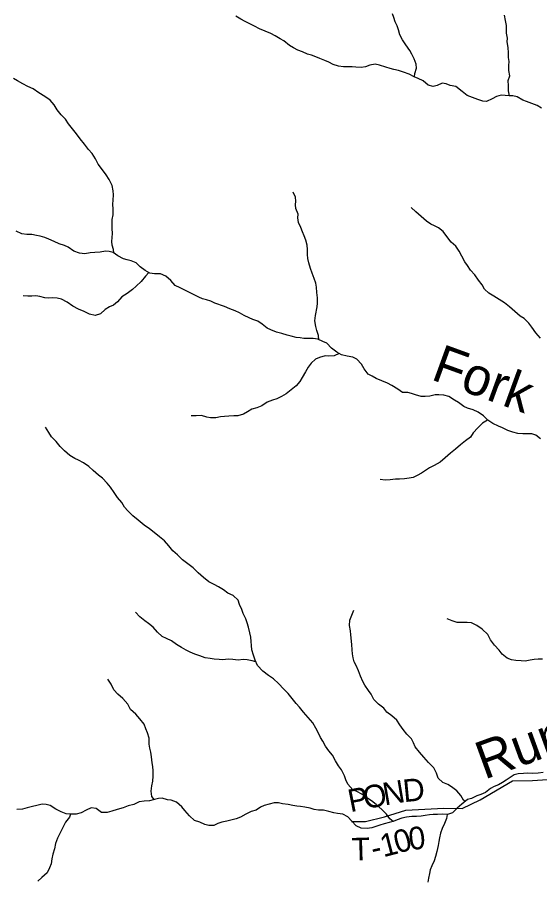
# Model space of a CAD drawing. Extents: x 1624196 to 2029251, y 146837 to 440034.
# Drawn here: x 1775938 to 1782867, y 237961 to 249407 of the extents above; entities that cross this region are included whole.
import ezdxf

# ---------------------------------------------------------------- set-up
doc = ezdxf.new("R2010")
doc.units = 0
for name, color, linetype in [('GM_X_Minor_River', 7, 'Continuous'), ('GM_X_Minor_River_Text', 7, 'Continuous'), ('GM_X_Township_Road', 7, 'Continuous'), ('GM_X_Township_Road_Text', 7, 'Continuous')]:
    doc.layers.add(name, color=color, linetype=linetype)

msp = doc.modelspace()

# ---------------------------------------------------------------- linework, layer by layer
at = {"layer": 'GM_X_Minor_River'}
for points in [[(1782892, 248200), (1782832, 248237), (1782762, 248261), (1782691, 248290), (1782641, 248308), (1782569, 248351), (1782511, 248363), (1782461, 248363), (1782407, 248368), (1782357, 248372), (1782293, 248356), (1782238, 248323), (1782162, 248291), (1782111, 248295), (1782045, 248316), (1781975, 248340), (1781903, 248367), (1781839, 248423), (1781753, 248490), (1781681, 248500), (1781627, 248525), (1781575, 248533), (1781509, 248501), (1781454, 248489), (1781386, 248504), (1781320, 248562), (1781254, 248593), (1781200, 248617), (1781136, 248652), (1781062, 248680), (1780992, 248699), (1780932, 248713), (1780882, 248729), (1780828, 248746), (1780740, 248770), (1780686, 248785), (1780615, 248771), (1780557, 248749), (1780497, 248742), (1780428, 248744), (1780378, 248748), (1780328, 248751), (1780264, 248749), (1780198, 248759), (1780128, 248780), (1780068, 248812), (1780018, 248832), (1779951, 248861), (1779899, 248881), (1779841, 248902), (1779789, 248918), (1779723, 248948), (1779661, 248971), (1779603, 249001), (1779549, 249034), (1779475, 249096), (1779425, 249119), (1779359, 249159), (1779299, 249190), (1779227, 249222), (1779149, 249253), (1779085, 249289), (1779031, 249315), (1778961, 249352), (1778903, 249382), (1778837, 249423)], [(1781205, 248615), (1781209, 248659), (1781233, 248731), (1781227, 248783), (1781200, 248854), (1781170, 248916), (1781144, 248968), (1781091, 249041), (1781045, 249107), (1781011, 249172), (1780992, 249242), (1780976, 249294), (1780952, 249347), (1780930, 249403), (1780913, 249453)], [(1782465, 248363), (1782454, 248430), (1782452, 248498), (1782448, 248566), (1782469, 248630), (1782457, 248702), (1782458, 248766), (1782460, 248821), (1782452, 248875), (1782455, 248937), (1782447, 249007), (1782436, 249079), (1782438, 249130), (1782426, 249196), (1782427, 249246), (1782427, 249296), (1782411, 249362), (1782402, 249435)], [(1777220, 246278), (1777212, 246324), (1777198, 246382), (1777194, 246432), (1777197, 246484), (1777199, 246539), (1777197, 246603), (1777198, 246721), (1777209, 246787), (1777209, 246859), (1777207, 246928), (1777210, 246980), (1777214, 247050), (1777211, 247104), (1777195, 247176), (1777157, 247253), (1777118, 247315), (1777070, 247384), (1777012, 247458), (1776976, 247530), (1776929, 247601), (1776883, 247653), (1776829, 247724), (1776771, 247792), (1776722, 247861), (1776672, 247927), (1776618, 247994), (1776576, 248056), (1776521, 248113), (1776467, 248179), (1776425, 248245), (1776373, 248306), (1776303, 248354), (1776225, 248405), (1776149, 248456), (1776079, 248488), (1776011, 248522), (1775941, 248563), (1775887, 248593)], [(1779939, 245127), (1779932, 245184), (1779912, 245252), (1779899, 245302), (1779883, 245378), (1779892, 245450), (1779916, 245563), (1779921, 245613), (1779921, 245683), (1779910, 245755), (1779906, 245825), (1779898, 245876), (1779877, 245940), (1779851, 246010), (1779825, 246074), (1779806, 246149), (1779790, 246205), (1779788, 246257), (1779789, 246327), (1779783, 246381), (1779763, 246450), (1779742, 246508), (1779720, 246560), (1779698, 246617), (1779669, 246685), (1779659, 246745), (1779663, 246795), (1779632, 246868), (1779630, 246918), (1779634, 246968), (1779627, 247018), (1779597, 247084)], [(1782878, 245147), (1782814, 245219), (1782761, 245296), (1782723, 245346), (1782661, 245411), (1782607, 245441), (1782467, 245566), (1782402, 245617), (1782330, 245663), (1782258, 245704), (1782194, 245744), (1782136, 245797), (1782104, 245855), (1782054, 245917), (1782008, 245988), (1781949, 246050), (1781909, 246113), (1781873, 246163), (1781833, 246237), (1781800, 246302), (1781756, 246368), (1781692, 246421), (1781634, 246499), (1781585, 246564), (1781523, 246614), (1781473, 246641), (1781423, 246663), (1781367, 246703), (1781295, 246762), (1781223, 246824), (1781163, 246881)], [(1780985, 244470), (1780905, 244522), (1780849, 244549), (1780771, 244581), (1780699, 244614), (1780645, 244642), (1780593, 244671), (1780539, 244741), (1780504, 244801), (1780440, 244870), (1780388, 244898), (1780312, 244909), (1780240, 244925), (1780176, 244964), (1780106, 245016), (1780042, 245081), (1779992, 245103), (1779924, 245134), (1779864, 245142), (1779789, 245142), (1779739, 245145), (1779689, 245151), (1779639, 245159), (1779569, 245174), (1779517, 245188), (1779447, 245210), (1779374, 245229), (1779302, 245259), (1779252, 245280), (1779184, 245334), (1779130, 245375), (1779064, 245397), (1779012, 245417), (1778948, 245448), (1778884, 245486), (1778826, 245511), (1778758, 245537), (1778686, 245570), (1778558, 245614), (1778504, 245637), (1778446, 245657), (1778396, 245672), (1778344, 245694), (1778286, 245722), (1778222, 245753), (1778168, 245779), (1778100, 245814), (1778034, 245846), (1777974, 245913), (1777908, 245971), (1777836, 246004), (1777760, 246002), (1777697, 246010), (1777633, 246047), (1777569, 246095), (1777516, 246148), (1777450, 246176), (1777397, 246187), (1777347, 246203), (1777273, 246241), (1777209, 246286), (1777157, 246300), (1777107, 246303), (1777037, 246289), (1776967, 246285), (1776904, 246282), (1776832, 246266), (1776764, 246278), (1776690, 246303), (1776612, 246355), (1776562, 246376), (1776492, 246400), (1776426, 246433), (1776355, 246461), (1776303, 246486), (1776241, 246500), (1776191, 246512), (1776133, 246523), (1776065, 246525), (1775999, 246535), (1775925, 246568)], [(1777681, 246020), (1777637, 245969), (1777580, 245901), (1777516, 245839), (1777465, 245795), (1777395, 245743), (1777324, 245698), (1777265, 245630), (1777213, 245584), (1777161, 245566), (1777102, 245529), (1777042, 245473), (1776973, 245447), (1776895, 245466), (1776823, 245504), (1776751, 245535), (1776673, 245575), (1776601, 245628), (1776523, 245666), (1776469, 245679), (1776409, 245683), (1776357, 245679), (1776304, 245684), (1776236, 245700), (1776186, 245708), (1776132, 245707), (1776080, 245707), (1776014, 245709)], [(1780207, 244945), (1780141, 244912), (1780071, 244908), (1780021, 244912), (1779948, 244891), (1779894, 244871), (1779837, 244817), (1779797, 244765), (1779760, 244701), (1779716, 244627), (1779685, 244575), (1779635, 244516), (1779572, 244462), (1779504, 244408), (1779441, 244376), (1779379, 244345), (1779323, 244327), (1779250, 244299), (1779182, 244252), (1779115, 244222), (1779051, 244206), (1778992, 244170), (1778940, 244141), (1778864, 244119), (1778811, 244119), (1778745, 244114), (1778687, 244108), (1778635, 244102), (1778570, 244093), (1778502, 244091), (1778450, 244099), (1778380, 244120), (1778310, 244118), (1778243, 244117)], [(1782878, 243811), (1782814, 243862), (1782764, 243880), (1782714, 243878), (1782643, 243877), (1782575, 243885), (1782509, 243902), (1782443, 243922), (1782373, 243957), (1782319, 243981), (1782247, 244017), (1782179, 244058), (1782121, 244116), (1782051, 244167), (1781983, 244199), (1781911, 244220), (1781861, 244240), (1781791, 244295), (1781737, 244325), (1781663, 244374), (1781597, 244390), (1781529, 244397), (1781479, 244397), (1781408, 244379), (1781346, 244374), (1781296, 244374), (1781220, 244398), (1781168, 244413), (1781118, 244425), (1781049, 244425), (1780985, 244470)], [(1782176, 244061), (1782110, 244018), (1782046, 243960), (1781983, 243893), (1781949, 243833), (1781882, 243785), (1781816, 243733), (1781749, 243675), (1781684, 243620), (1781614, 243560), (1781545, 243502), (1781467, 243459), (1781406, 243429), (1781352, 243393), (1781301, 243355), (1781243, 243325), (1781187, 243298), (1781136, 243290), (1781074, 243282), (1781006, 243277), (1780956, 243277), (1780885, 243269), (1780815, 243264), (1780753, 243274)], [(1780922, 238734), (1780877, 238768), (1780834, 238833), (1780772, 238893), (1780698, 238958), (1780634, 239006), (1780572, 239047), (1780506, 239095), (1780440, 239132), (1780388, 239156), (1780324, 239231), (1780295, 239287), (1780279, 239341), (1780237, 239418), (1780199, 239472), (1780158, 239540), (1780118, 239613), (1780070, 239671), (1780026, 239734), (1779991, 239800), (1779959, 239850), (1779931, 239905), (1779897, 239971), (1779858, 240043), (1779794, 240116), (1779734, 240184), (1779682, 240251), (1779639, 240301), (1779583, 240366), (1779531, 240434), (1779473, 240491), (1779401, 240565), (1779338, 240626), (1779272, 240670), (1779194, 240729), (1779126, 240803), (1779094, 240874), (1779069, 240940), (1779051, 241012), (1779043, 241070), (1779040, 241123), (1779034, 241181), (1779022, 241237), (1779003, 241313), (1778989, 241371), (1778969, 241424), (1778936, 241494), (1778914, 241546), (1778886, 241613), (1778868, 241673), (1778801, 241733), (1778732, 241766), (1778671, 241808), (1778605, 241847), (1778551, 241879), (1778477, 241914), (1778407, 241972), (1778335, 242033), (1778271, 242099), (1778201, 242154), (1778129, 242208), (1778061, 242273), (1777999, 242327), (1777948, 242390), (1777890, 242458), (1777824, 242511), (1777754, 242567), (1777690, 242618), (1777620, 242668), (1777542, 242733), (1777470, 242792), (1777403, 242856), (1777361, 242907), (1777323, 242967), (1777265, 243033), (1777223, 243100), (1777176, 243170), (1777132, 243223), (1777066, 243289), (1777014, 243328), (1776946, 243390), (1776888, 243445), (1776818, 243495), (1776750, 243530), (1776700, 243552), (1776636, 243590), (1776563, 243651), (1776505, 243711), (1776455, 243778), (1776391, 243838), (1776357, 243895), (1776310, 243967)], [(1781878, 238999), (1781856, 239015), (1781819, 239078), (1781767, 239140), (1781699, 239195), (1781647, 239223), (1781583, 239252), (1781521, 239308), (1781499, 239374), (1781464, 239445), (1781394, 239517), (1781328, 239586), (1781274, 239652), (1781217, 239725), (1781195, 239779), (1781165, 239829), (1781105, 239894), (1781057, 239954), (1781010, 240017), (1780970, 240079), (1780906, 240138), (1780838, 240186), (1780798, 240236), (1780730, 240291), (1780669, 240353), (1780633, 240422), (1780595, 240472), (1780549, 240543), (1780520, 240593), (1780490, 240663), (1780464, 240732), (1780432, 240802), (1780407, 240854), (1780393, 240904), (1780385, 240961), (1780378, 241013), (1780376, 241083), (1780363, 241209), (1780357, 241265), (1780346, 241336), (1780350, 241404), (1780376, 241470), (1780401, 241538)], [(1779103, 240854), (1779054, 240864), (1778986, 240880), (1778936, 240885), (1778867, 240875), (1778797, 240885), (1778733, 240886), (1778665, 240880), (1778615, 240882), (1778548, 240889), (1778496, 240895), (1778428, 240906), (1778358, 240934), (1778294, 240954), (1778232, 240981), (1778180, 241007), (1778116, 241044), (1778050, 241082), (1777982, 241133), (1777918, 241163), (1777858, 241191), (1777798, 241248), (1777738, 241312), (1777680, 241363), (1777628, 241395), (1777562, 241448), (1777505, 241510)], [(1782904, 240890), (1782848, 240890), (1782793, 240885), (1782741, 240875), (1782675, 240861), (1782621, 240864), (1782550, 240872), (1782492, 240878), (1782434, 240901), (1782370, 240953), (1782328, 241006), (1782269, 241074), (1782215, 241145), (1782177, 241217), (1782105, 241284), (1782035, 241334), (1781963, 241369), (1781903, 241375), (1781837, 241375), (1781771, 241374), (1781707, 241396), (1781641, 241425)], [(1777753, 239025), (1777722, 239067), (1777715, 239135), (1777723, 239207), (1777735, 239271), (1777740, 239334), (1777740, 239408), (1777735, 239462), (1777727, 239514), (1777719, 239590), (1777708, 239653), (1777696, 239705), (1777688, 239761), (1777685, 239841), (1777667, 239911), (1777643, 239962), (1777620, 240026), (1777562, 240096), (1777512, 240159), (1777440, 240221), (1777403, 240292), (1777337, 240364), (1777273, 240425), (1777217, 240483), (1777185, 240556), (1777138, 240624)], [(1782914, 239384), (1782848, 239377), (1782776, 239371), (1782706, 239376), (1782651, 239372), (1782581, 239368), (1782527, 239352), (1782474, 239317), (1782422, 239283), (1782372, 239251), (1782319, 239221), (1782265, 239198), (1782215, 239170), (1782146, 239118), (1782084, 239092), (1782033, 239073), (1781963, 239041), (1781909, 239025), (1781836, 238963), (1781773, 238910), (1781709, 238848), (1781643, 238826), (1781578, 238833), (1781512, 238827), (1781456, 238825), (1781406, 238822), (1781347, 238814), (1781293, 238806), (1781231, 238802), (1781171, 238799), (1781100, 238791), (1781038, 238778), (1780976, 238754), (1780923, 238734), (1780869, 238720), (1780803, 238703), (1780746, 238683), (1780694, 238667), (1780642, 238651), (1780580, 238640), (1780501, 238644), (1780431, 238675), (1780377, 238737), (1780324, 238796), (1780254, 238832), (1780187, 238838), (1780137, 238849), (1780069, 238867), (1779999, 238884), (1779933, 238884), (1779877, 238892), (1779821, 238909), (1779750, 238923), (1779696, 238931), (1779646, 238936), (1779592, 238946), (1779530, 238958), (1779454, 238969), (1779402, 238983), (1779347, 238982), (1779277, 238962), (1779213, 238948), (1779162, 238924), (1779108, 238883), (1779040, 238865), (1778969, 238833), (1778897, 238792), (1778840, 238768), (1778770, 238750), (1778718, 238737), (1778649, 238723), (1778597, 238709), (1778547, 238679), (1778478, 238680), (1778426, 238694), (1778358, 238725)], [(1778358, 238725), (1778290, 238747), (1778224, 238808), (1778159, 238878), (1778119, 238928), (1778049, 238989), (1777979, 239015), (1777929, 239022), (1777860, 239044), (1777810, 239040), (1777758, 239027), (1777690, 239007), (1777623, 239005), (1777555, 238994), (1777485, 238960), (1777410, 238940), (1777342, 238913), (1777263, 238893), (1777191, 238870), (1777129, 238854), (1777054, 238854), (1776985, 238907), (1776916, 238915), (1776852, 238886), (1776785, 238848), (1776719, 238832), (1776655, 238829), (1776587, 238835), (1776519, 238861), (1776451, 238896), (1776375, 238944), (1776322, 238959), (1776266, 238963), (1776196, 238945), (1776140, 238932), (1776071, 238914), (1776005, 238896), (1775931, 238895)], [(1776645, 238829), (1776629, 238791), (1776576, 238723), (1776539, 238645), (1776511, 238591), (1776470, 238513), (1776446, 238443), (1776433, 238373), (1776411, 238301), (1776396, 238239), (1776386, 238172), (1776365, 238120), (1776333, 238052), (1776264, 237991), (1776210, 237943)], [(1781641, 238826), (1781630, 238774), (1781604, 238706), (1781571, 238642), (1781551, 238580), (1781540, 238518), (1781528, 238466), (1781520, 238414), (1781503, 238334), (1781486, 238268), (1781466, 238210), (1781434, 238144), (1781415, 238094), (1781405, 238042), (1781390, 237980), (1781382, 237928)]]:
    msp.add_lwpolyline(points, dxfattribs=at)
at = {"layer": 'GM_X_Township_Road'}
msp.add_lwpolyline([(1780370, 238735), (1780555, 238734), (1780807, 238797), (1781091, 238883), (1781595, 238909), (1781840, 238906), (1782077, 239023), (1782506, 239275), (1782773, 239278), (1783100, 239302)], dxfattribs=at)

# ---------------------------------------------------------------- texts
at = {"layer": 'GM_X_Minor_River_Text'}
for s, rotation, p in [('Fork', 339.9986, (1781410, 244605)), ('Run', 20.0007, (1782133, 239287))]:
    msp.add_text(s, height=500, rotation=rotation, dxfattribs=at).set_placement(p)
at = {"layer": 'GM_X_Township_Road_Text'}
for s, rotation, p in [('N', 9.727, (1780811, 238946)), ('D', 5.3974, (1781066, 238990)), ('P', 11.1748, (1780356, 238856)), ('O', 11.161, (1780554, 238895)), ('0', 6.2232, (1781143, 238353)), ('1', 14.3972, (1780793, 238258)), ('0', 15.5182, (1780978, 238306)), ('T', 1.7274, (1780377, 238215)), ('-', 12.1878, (1780660, 238229))]:
    msp.add_text(s, height=300, rotation=rotation, dxfattribs=at).set_placement(p)

doc.saveas('drawing.dxf')
